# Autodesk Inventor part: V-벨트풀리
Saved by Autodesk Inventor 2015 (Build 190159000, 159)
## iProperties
Created: 2025-08
Part Number: V-벨트풀리
Material: 일반
Document SubType Name: Modeling
Designer: USER
Density: 1 g/cm^3
Appearance: 기본값
Author: jhkim
Creation Date: 2025-08-05
Sending System: Autodesk Inventor 2026
Preprocessor: ST-DEVELOPER v20.1
Author: USER
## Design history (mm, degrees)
node "V-벨트풀리1"
node "솔리드1"
node "기준1"
